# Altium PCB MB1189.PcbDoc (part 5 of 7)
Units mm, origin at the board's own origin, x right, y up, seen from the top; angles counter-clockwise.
Board outline 60.03 x 127.03 mm, 6 copper layers (TOP, L2_GND, L3_VCC, L4_SIG, L5_GND, BOTTOM), stack 1.58 mm thick; 273 components, 264 nets, 1114 pads, 811 vias.
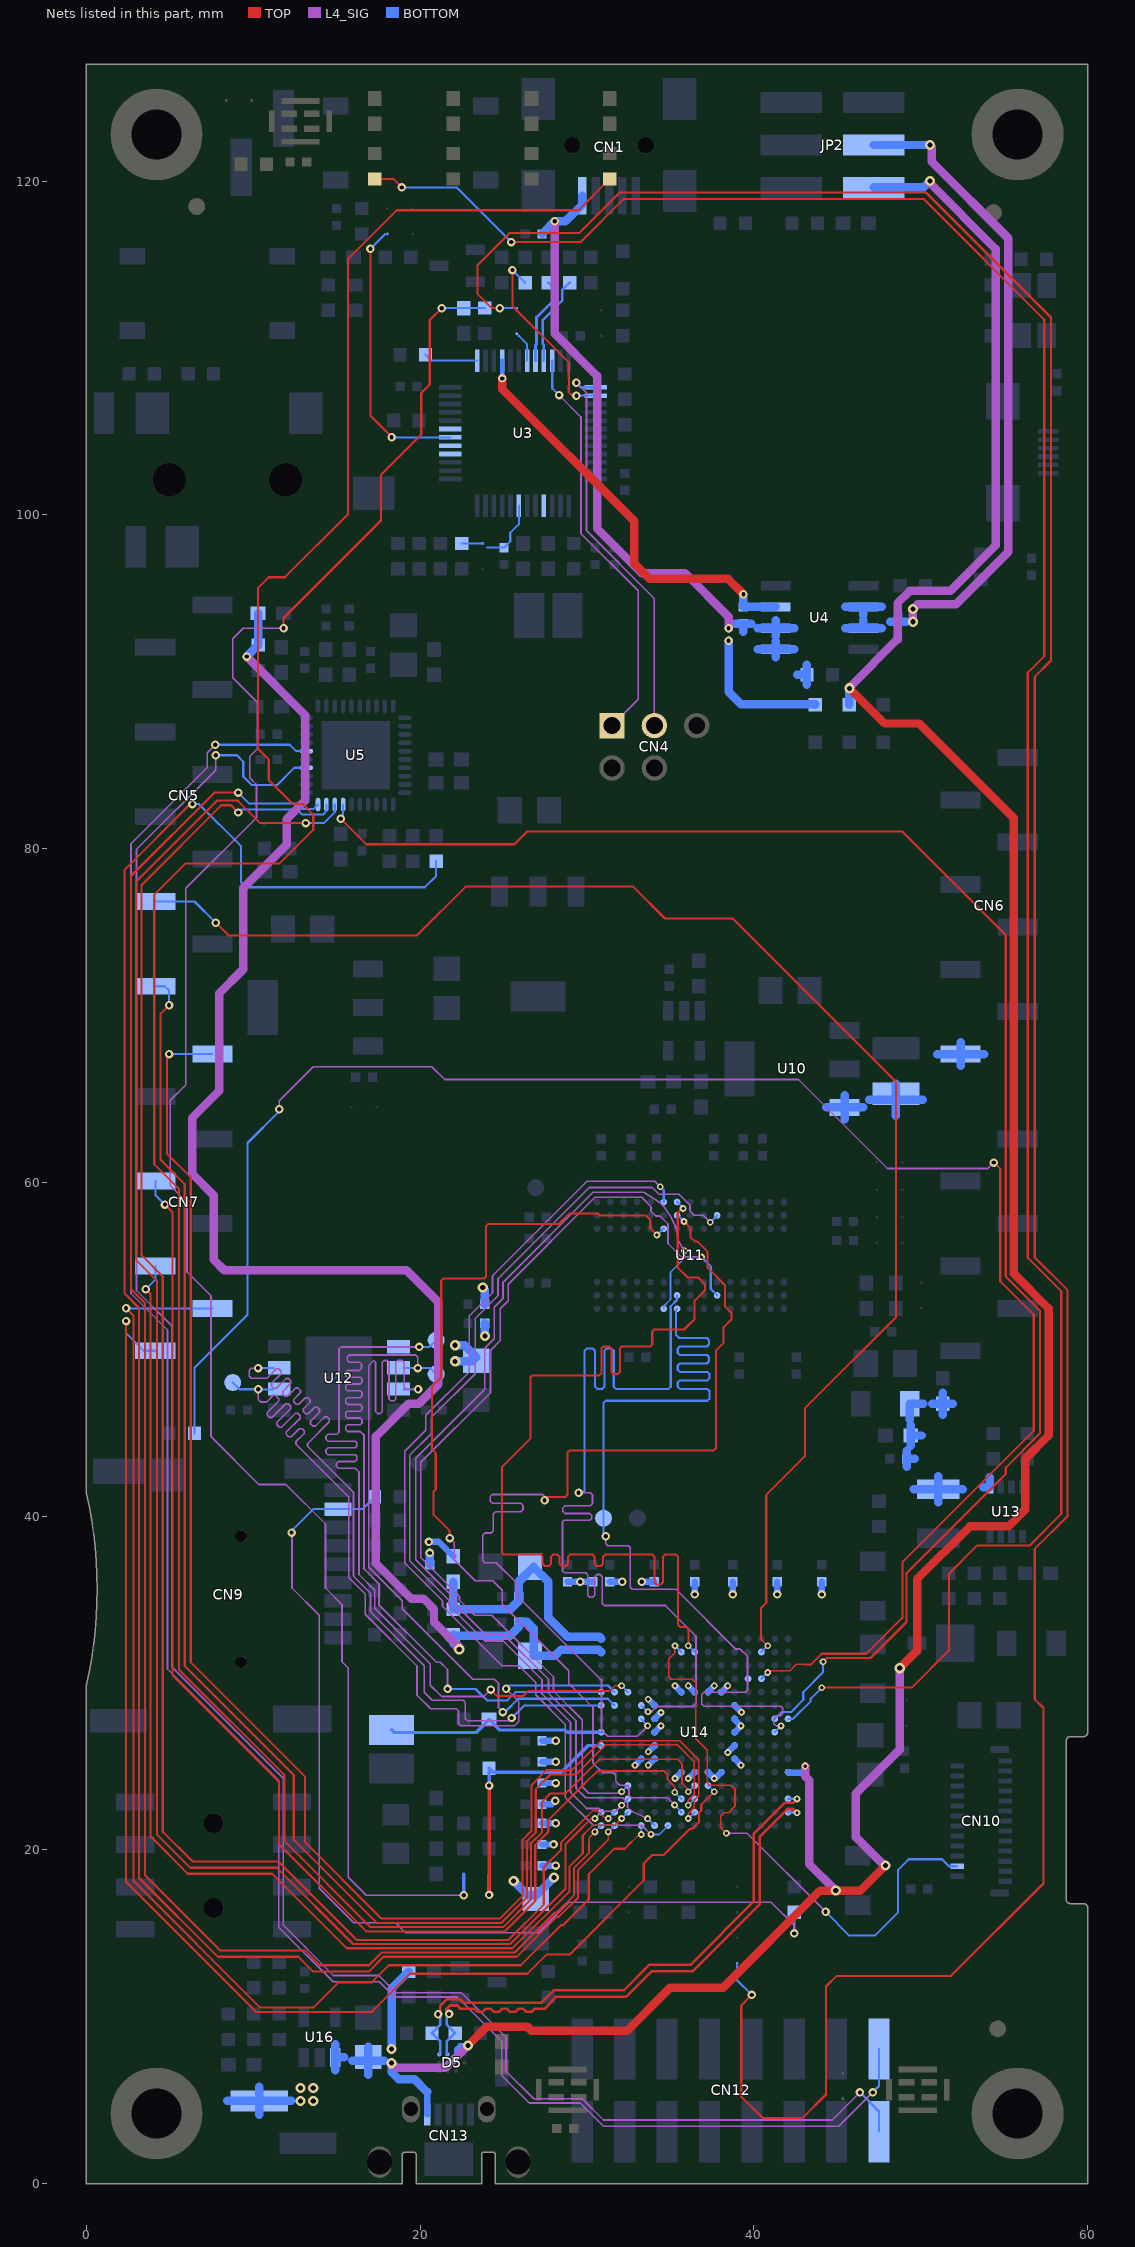
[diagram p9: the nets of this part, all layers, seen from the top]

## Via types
v1: diameter 0.61/0.61/0.61 (per signal layer), hole 0.305, TOP to BOTTOM, 321 vias
v2: diameter 0.508/0.508/0.508 (per signal layer), hole 0.254, TOP to BOTTOM, 247 vias
v3: diameter 0.406/0.406/0.406 (per signal layer), hole 0.203, TOP to BOTTOM, 243 vias

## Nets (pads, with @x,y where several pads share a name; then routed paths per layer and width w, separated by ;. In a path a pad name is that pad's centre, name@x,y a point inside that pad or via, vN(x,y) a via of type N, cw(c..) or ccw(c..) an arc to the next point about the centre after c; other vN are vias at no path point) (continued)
PE0: U11.K9 U14.A6 | length 58.9
  L4_SIG w0.102: v3(33.833,20.921) 33.816,20.921 33.274,21.463 30.378,21.463 28.702,23.139 28.702,27.511 26.924,29.289 26.924,30.023 25.921,31.026 24.905,31.026 21.336,34.595 21.336,34.925 19.075,37.186 19.075,43.891 20.333,45.148 20.333,46.038 22.936,48.641 22.936,51.994 24.333,53.391 24.333,54.407 29.997,60.071 34.061,60.071 v3(34.392,59.741)
  BOTTOM w0.102: v3(33.833,20.921) 34.319,20.921 U14.A6@34.849,21.451
  BOTTOM w0.127: v3(34.392,59.741) 34.595,59.537 U11.K9@34.595,58.826
PE1: U11.K1 U14.A5 | length 61.9
  L4_SIG w0.102: v3(33.631,21.869) 32.69,22.301 32.427,22.564 32.427,22.821 32.13,23.118 29.917,23.118 29.337,23.698 29.337,27.739 27.686,29.39 27.686,30.229 24.986,32.928 23.891,32.928 22.047,34.773 22.047,35.076 19.736,37.388 19.736,43.459 23.876,47.6 23.876,50.063 24.435,50.622 24.435,52.527 24.968,53.061 24.968,54.026 30.353,59.411 33.401,59.411 34.392,58.776 34.557,58.61 35.049,57.896 35.361,57.22 35.464,56.527 v3(35.839,55.905)
  BOTTOM w0.102: U11.K1@34.595,52.426 34.595,52.578 35.001,52.984 35.001,54.61 35.839,55.448 v3(35.839,55.905)
  BOTTOM w0.127: v3(33.631,21.869) U14.A5@34.049,21.451
PE3: R46.2 U14.A2 | length 121.3
  TOP w0.102: 31.14,20.472 31.272,20.604 v3(31.272,21.074)
  TOP w0.127: v2(6.35,82.677) 6.223,82.677 2.286,78.74 2.286,53.34 3.15,52.476 3.15,18.313 7.874,13.589 12.7,13.589 13.589,12.7 16.913,12.7 17.802,13.589 25.781,13.589 28.181,15.989 28.308,15.989 29.464,17.145 29.464,18.796 31.14,20.472
  BOTTOM w0.102: v3(31.272,21.074) U14.A2@31.649,21.451
  BOTTOM w0.127: v2(6.35,82.677) 6.731,82.677 9.271,80.137 9.271,77.978 9.563,77.686 20.282,77.686 20.955,78.359 R46.2@20.955,79.248
PE4: U5.40 U14.A1 | length 108.6
  TOP w0.102: 30.128,20.472 30.128,20.73 v3(30.472,21.074)
  TOP w0.127: v2(9.093,83.363) 7.671,83.363 2.667,78.359 2.667,53.594 3.505,52.756 3.505,18.466 8.001,13.97 13.081,13.97 13.97,13.081 16.934,13.081 17.696,13.843 25.676,13.843 28.076,16.243 28.203,16.243 29.21,17.25 29.21,18.901 30.128,19.82 30.128,20.472
  BOTTOM w0.102: v3(30.472,21.074) U14.A1@30.849,21.451
  BOTTOM w0.127: v2(9.093,83.363) 9.754,82.702 12.634,82.702 12.952,82.384 13.615,82.384 U5.40@13.879,82.648
PE5: U5.38 U14.B1 | length 107
  TOP w0.102: 29.87,21.488 30.256,21.874 v3(30.472,21.874)
  TOP w0.127: v2(13.144,81.534) 10.414,81.534 9.068,82.88 7.823,82.88 2.975,78.032 2.975,55.344 4.216,54.102 4.216,20.93 6.223,18.923 11.405,18.923 15.977,14.351 25.4,14.351 28.702,17.653 28.702,20.32 29.87,21.488
  BOTTOM w0.102: v3(30.472,21.874) U14.B1@30.849,22.251
  BOTTOM w0.127: v2(13.144,81.534) 14.224,81.534 14.879,82.189 U5.38@14.879,82.648
PE6: U5.39 U14.B2 | length 106.1
  TOP w0.102: 29.87,21.869 30.353,22.352 30.607,22.352 31.085,21.874 v3(31.272,21.874)
  TOP w0.127: v2(9.093,82.169) 8.661,82.601 8.077,82.601 3.302,77.826 3.302,55.626 4.572,54.356 4.572,21.082 6.35,19.304 11.481,19.304 16.18,14.605 25.295,14.605 27.407,16.717 27.407,18.971 28.448,20.012 28.448,20.447 29.87,21.869
  BOTTOM w0.102: v3(31.272,21.874) U14.B2@31.649,22.251
  BOTTOM w0.127: v2(9.093,82.169) 9.271,82.347 12.631,82.347 12.935,82.042 14.173,82.042 14.379,82.248 U5.39@14.379,82.648
PF6: U12.7 U14.K2 | length 48.2
  L4_SIG w0.102: v2(19.875,47.599) 19.177,47.599 19.05,47.726 19.05,49.2 18.923,49.327 18.641,49.327 18.539,49.225 18.539,47.015 18.438,46.914 18.234,46.914 18.133,47.015 18.133,49.225 18.031,49.327 17.828,49.327 17.726,49.225 17.726,46.271 17.607,46.152 17.439,46.152 17.32,46.271 17.32,49.225 17.218,49.327 16.916,49.025 16.916,36.932 18.923,34.925 18.923,34.455 23.152,30.226 24.435,30.226 24.689,29.972 24.689,28.522 v2(24.954,28.258)
  BOTTOM w0.127: U12.7@19.013,47.599 v2(19.875,47.599) ; v2(24.954,28.258) 25.082,28.258 25.88,29.055 31.245,29.055 U14.K2@31.649,28.651
PF7: U12.3 U14.K1 | length 48
  L4_SIG w0.102: v2(10.287,48.869) 9.881,48.87 9.754,48.743 9.754,48.387 9.881,48.26 10.82,48.26 10.988,48.428 11.383,48.823 11.527,48.823 11.671,48.679 11.671,48.536 11.09,47.955 11.09,47.787 11.209,47.668 11.377,47.668 11.958,48.248 12.102,48.248 12.246,48.104 12.246,47.961 11.754,47.469 11.754,47.301 11.873,47.182 12.041,47.182 12.533,47.673 12.677,47.673 12.821,47.529 12.821,47.386 12.426,46.991 12.426,46.848 12.57,46.703 12.713,46.703 13.108,47.098 13.252,47.098 13.396,46.954 13.396,46.811 13.001,46.416 13.001,46.272 13.145,46.128 13.288,46.128 13.683,46.523 13.827,46.523 13.971,46.379 13.971,46.236 13.431,45.696 13.431,45.523 13.553,45.4 13.726,45.4 14.265,45.939 14.437,45.939 14.558,45.818 14.558,45.647 13.246,44.336 13.246,44.183 16.002,41.427 16.002,36.398 17.018,35.382 17.018,34.265 20.244,31.039 20.244,29.439 20.726,28.956 22.581,28.956 22.708,28.829 22.708,27.864 22.835,27.737 25.352,27.737 25.479,27.864 v2(25.479,27.9)
  BOTTOM w0.127: v2(10.287,48.869) U12.3@11.213,48.869 ; v2(25.479,27.9) 26.23,28.651 U14.K1@30.849,28.651
PF8: TP6.1 U12.5 U14.L3 | length 49.8
  TOP w0.102: 29.87,29.515 31.36,29.515 31.674,29.828 v3(32.072,29.828)
  TOP w0.127: v2(24.232,29.604) 24.625,29.21 26.162,29.21 26.467,29.515 29.87,29.515
  L4_SIG w0.102: v2(19.939,50.139) 15.265,50.139 15.138,50.012 15.138,45.027 15.011,44.9 14.47,44.9 14.351,44.781 14.351,44.613 14.47,44.494 16.104,44.494 16.205,44.392 16.205,44.189 16.104,44.088 14.47,44.088 14.351,43.968 14.351,43.8 14.47,43.681 16.104,43.681 16.205,43.58 16.205,43.376 16.104,43.275 15.088,43.275 14.986,43.173 14.986,42.97 15.088,42.868 16.104,42.868 16.332,42.64 16.332,36.5 17.272,35.56 17.272,34.468 20.599,31.14 20.599,29.87 21.285,29.185 23.812,29.185 v2(24.232,29.604)
  BOTTOM w0.127: U12.5@19.013,50.139 v2(19.939,50.139) 20.548,50.139 TP6.1@20.955,50.546 ; v3(32.072,29.828) U14.L3@32.449,29.451
PF9: TP7.1 U12.2 U14.L2 | length 49.6
  L4_SIG w0.102: v2(10.288,47.6) 10.288,46.989 10.439,46.838 10.795,46.838 11.201,47.244 11.328,47.244 11.532,47.041 11.532,46.901 10.836,46.205 10.836,46.035 10.956,45.914 11.127,45.914 11.948,46.735 12.091,46.735 12.235,46.591 12.235,46.447 11.401,45.613 11.401,45.47 11.545,45.326 11.689,45.326 12.523,46.16 12.666,46.16 12.81,46.016 12.81,45.872 11.976,45.038 11.976,44.895 12.12,44.751 12.264,44.751 12.755,45.242 12.924,45.242 13.043,45.123 13.043,44.955 12.551,44.463 12.551,44.319 15.723,41.148 15.723,36.322 16.713,35.331 16.713,34.112 19.812,31.013 19.812,29.261 20.625,28.448 22.174,28.448 22.301,28.321 22.301,27.559 22.428,27.432 25.654,27.432 25.911,27.689 25.911,28.89 v2(25.146,29.654)
  BOTTOM w0.127: TP7.1@8.763,48.006 9.169,47.6 v2(10.288,47.6) ; v2(10.288,47.6) U12.2@11.213,47.599 ; v2(25.146,29.654) 25.336,29.845 31.255,29.845 U14.L2@31.649,29.451
PF10: TP5.1 U12.6 U14.L1 | length 48.1
  L4_SIG w0.102: v2(19.851,48.869) 19.851,49.53 19.724,49.657 15.748,49.657 15.621,49.53 15.621,49.352 15.748,49.225 16.358,49.225 16.485,49.098 16.485,48.853 16.358,48.726 15.646,48.726 15.545,48.625 15.545,48.422 15.646,48.32 16.408,48.32 16.51,48.218 16.51,48.015 16.408,47.914 15.646,47.914 15.545,47.812 15.545,47.609 15.646,47.507 16.408,47.507 16.51,47.406 16.51,47.202 16.408,47.101 15.646,47.101 15.545,46.999 15.545,46.796 15.646,46.694 16.408,46.694 16.51,46.593 16.51,46.39 16.408,46.288 15.646,46.288 15.545,46.186 15.545,45.983 15.646,45.882 16.408,45.882 16.51,45.78 16.51,45.577 16.408,45.475 15.646,45.475 15.545,45.374 15.545,45.17 15.646,45.069 16.408,45.069 16.637,44.84 16.637,36.83 17.526,35.941 17.526,34.696 20.98,31.242 21.209,31.242 21.641,30.81 v2(21.641,29.642)
  BOTTOM w0.127: U12.6@19.013,48.869 v2(19.851,48.869) 20.6,48.869 TP5.1@20.955,48.514 ; v2(21.641,29.642) 23.317,29.642 24.003,28.956 25.222,28.956 25.717,29.451 U14.L1@30.849,29.451
PF11: U11.J9 U14.P8 | length 59
  TOP w0.127: v3(35.757,58.434) 35.689,58.434 35.433,58.178 35.433,54.889 36.017,54.305 36.652,54.305 37.059,53.899 37.059,53.518 36.449,52.908 36.449,51.816 35.814,51.181 34.036,51.181 33.909,51.054 33.909,50.292 33.782,50.165 32.092,50.165 31.965,50.038 31.965,48.641 31.838,48.514 31.584,48.514 31.457,48.641 31.457,50.038 31.33,50.165 30.988,50.165 30.861,50.038 30.861,48.565 30.734,48.438 26.733,48.438 26.607,48.311 26.607,44.64 24.892,42.926 24.892,37.821 25.019,37.694 27.211,37.694 27.338,37.567 27.338,37.135 27.465,37.008 27.719,37.008 27.846,37.135 27.846,37.567 27.973,37.694 28.227,37.694 28.354,37.567 28.354,37.135 28.481,37.008 28.735,37.008 28.862,37.135 28.862,37.567 28.989,37.694 30.325,37.694 30.452,37.567 30.452,37.135 30.579,37.008 30.833,37.008 30.96,37.135 30.96,37.567 31.087,37.694 33.912,37.694 34.039,37.567 34.039,36.017 34.166,35.89 34.42,35.89 34.547,36.017 34.547,37.567 34.674,37.694 35.331,37.694 35.458,37.567 35.458,33.477 35.585,33.35 35.945,33.35 36.072,33.223 v3(36.072,32.228)
  BOTTOM w0.127: U11.J9@35.395,58.826 35.408,58.826 35.757,58.477 v3(35.757,58.434) ; v3(36.072,32.228) U14.P8@36.449,31.851
PG2: R57.1 U14.M13 | length 109.9
  TOP w0.102: v3(40.826,30.628) 40.932,30.734 42.164,30.734 42.545,31.115 43.028,31.115
  TOP w0.127: 43.028,31.115 43.434,31.115 44.069,31.75 46.736,31.75 48.895,33.909 48.895,37.236 56.769,45.11 56.769,52.07 54.762,54.077 54.762,60.808 v2(54.381,61.189)
  L4_SIG w0.102: v2(11.557,64.389) 11.557,64.897 13.589,66.929 20.701,66.929 21.463,66.167 42.672,66.167 48.006,60.833 54.026,60.833 v2(54.381,61.189)
  BOTTOM w0.127: R57.1@6.477,44.958 6.477,48.895 9.652,52.07 9.652,62.357 11.557,64.262 v2(11.557,64.389) ; U14.M13@40.449,30.251 v3(40.826,30.628)
PG3: U14.M12
PG6: R2.1 U14.J15 | length 142.8
  TOP w0.127: R2.1@17.272,120.142 18.39,120.142 v2(18.898,119.634) ; v2(25.451,116.357) 29.616,116.357 32.207,118.948 50.165,118.948 57.404,111.709 57.404,91.542 56.413,90.551 56.413,55.474 58.42,53.467 58.42,40.132 56.515,38.227 53.365,38.227 51.689,36.551 51.689,31.953 49.454,29.718 v3(44.069,29.718)
  BOTTOM w0.127: v2(18.898,119.634) 22.174,119.634 v2(25.451,116.357) ; U14.J15@42.049,27.851 42.342,27.851 43.402,28.911 43.402,29.051 v3(44.069,29.718)
PG7: U5.37 U14.J14 | length 100.6
  TOP w0.127: v2(15.24,81.788) 16.764,80.264 25.654,80.264 26.416,81.026 48.895,81.026 55.093,74.828 55.093,54.356 57.15,52.299 57.15,44.958 55.093,42.901 55.093,42.52 49.149,36.576 49.149,33.655 46.99,31.496 44.374,31.496 v3(44.145,31.267)
  BOTTOM w0.127: v2(15.24,81.788) 15.379,81.927 U5.37@15.379,82.648 ; U14.J14@41.249,27.851 41.648,28.25 42.22,28.25 42.956,28.986 42.956,29.443 44.145,30.632 v3(44.145,31.267)
PG8: TP3.1 U11.J1 U14.H14 | length 58
  L4_SIG w0.102: v2(31.115,38.798) 31.115,38.354 31.242,38.227 32.461,38.227 32.588,38.1 32.588,35.738 32.715,35.611 35.331,35.611 38.913,32.029 39.188,32.029 39.62,31.598 39.62,29.566 39.493,29.439 37.008,29.439 36.881,29.312 36.881,28.728 37.008,28.601 41.605,28.601 41.732,28.474 41.732,28.169 41.605,28.042 41.326,28.042 41.199,27.915 41.199,27.555 41.326,27.428 v3(41.626,27.428)
  BOTTOM w0.127: v2(31.115,38.798) 30.988,38.925 TP3.1@30.988,39.878 30.988,46.787 31.115,46.914 37.211,46.914 37.338,47.041 37.338,47.498 37.211,47.625 35.56,47.625 35.433,47.752 35.433,48.006 35.56,48.133 37.211,48.133 37.338,48.26 37.338,48.514 37.211,48.641 35.56,48.641 35.433,48.768 35.433,49.022 35.56,49.149 37.186,49.149 37.313,49.276 37.313,49.53 37.186,49.657 35.56,49.657 35.433,49.784 35.433,50.038 35.56,50.165 37.186,50.165 37.313,50.292 37.313,50.546 37.186,50.673 35.522,50.673 35.331,50.863 35.331,52.363 U11.J1@35.395,52.426 ; U14.H14@41.249,27.051 v3(41.626,27.428)
PG9: CN7.1 U14.D9 | length 82.1
  TOP w0.127: v2(2.375,51.689) 2.375,18.072 10.16,10.287 17.094,10.287 19.38,12.573 26.416,12.573 27.559,13.716 28.951,13.716 33.401,18.166 33.401,19.177 33.909,19.685 34.596,19.685 36.158,21.247 36.305,21.247 36.703,21.645 36.703,22.209 36.847,22.353 36.847,22.694 v3(37.626,23.474)
  BOTTOM w0.102: U14.D9@37.249,23.851 v3(37.626,23.474)
  BOTTOM w0.127: v2(2.375,51.689) 2.375,50.965 3.429,49.911 CN7.1@4.127,49.911
PG10: CN5.1 U14.C8 | length 93
  TOP w0.102: 29.87,25.044 31.115,26.289 35.399,26.289 36.427,25.261 36.427,23.327 36.072,22.971 v3(36.072,22.674)
  TOP w0.127: v2(4.953,70.612) 4.445,70.104 4.445,61.341 5.893,59.893 5.893,31.013 12.421,24.486 12.421,20.599 17.399,15.621 24.873,15.621 26.391,17.139 26.391,20.505 26.924,21.039 26.924,23.622 27.813,24.511 29.337,24.511 29.87,25.044
  BOTTOM w0.127: CN5.1@4.127,71.755 4.699,71.755 4.953,71.501 v2(4.953,70.612) ; v3(36.072,22.674) U14.C8@36.449,23.051
PG11: CN7.8 U14.B8 | length 91.6
  TOP w0.102: 29.87,25.552 30.861,26.543 35.56,26.543 36.703,25.4 36.703,23.241 36.427,22.965 36.427,22.526 36.072,22.171 v3(36.072,21.874)
  TOP w0.127: v2(4.953,67.691) 4.826,67.564 4.826,61.722 6.248,60.3 6.248,31.242 13.106,24.384 13.106,20.447 17.678,15.875 24.768,15.875 26.137,17.244 26.137,20.611 26.67,21.144 26.67,23.876 27.559,24.765 29.083,24.765 29.87,25.552
  BOTTOM w0.127: v2(4.953,67.691) CN7.8@7.556,67.691 ; v3(36.072,21.874) U14.B8@36.449,22.251
PG12: CN7.5 U14.C7 | length 76.5
  TOP w0.102: 29.87,23.971 29.87,23.982 30.607,24.718 34.62,24.718 34.827,24.511 34.827,24.206 35.255,23.778 v3(35.255,23.444)
  TOP w0.127: v2(4.699,58.674) 5.156,58.217 5.156,30.455 11.532,24.079 11.532,20.345 16.764,15.113 25.084,15.113 26.899,16.928 26.899,20.295 27.673,21.069 27.673,21.774 29.87,23.971
  BOTTOM w0.127: CN7.5@4.127,60.071 4.127,59.245 v2(4.699,58.674) ; v3(35.255,23.444) U14.C7@35.649,23.051
PG13: CN7.3 U14.B3 | length 70.8
  TOP w0.102: 29.87,20.98 30.353,21.463 31.661,21.463 v3(32.072,21.874)
  TOP w0.127: v2(3.556,53.594) 3.835,53.315 3.835,20.803 6.071,18.567 11.125,18.567 15.596,14.097 25.527,14.097 28.956,17.526 28.956,19.007 29.743,19.794 29.743,20.853 29.87,20.98
  BOTTOM w0.102: v3(32.072,21.874) U14.B3@32.449,22.251
  BOTTOM w0.127: v2(3.556,53.594) 4.127,54.165 CN7.3@4.127,54.991
PG14: CN7.2 U14.A4 | length 79
  TOP w0.102: 32.664,20.472 33.11,20.918 v3(33.249,20.918)
  TOP w0.127: v2(2.375,52.451) 2.819,52.006 2.819,18.136 10.414,10.541 13.589,10.541 15.113,12.065 17.101,12.065 18.117,13.081 26.035,13.081 28.435,15.481 28.562,15.481 30.099,17.018 30.099,18.542 31.623,20.066 32.258,20.066 32.664,20.472
  BOTTOM w0.102: v3(33.249,20.918) U14.A4@33.249,21.451
  BOTTOM w0.127: v2(2.375,52.451) CN7.2@7.556,52.451
PG15: U11.K7 U14.B7 | length 58.7
  TOP w0.127: v2(21.768,38.684) 21.768,39.116 20.803,40.081 20.803,41.478 20.93,41.605 20.93,43.79 20.701,44.018 20.701,47.752 21.26,48.311 21.26,54.102 21.387,54.229 23.825,54.229 23.952,54.356 23.952,57.379 24.079,57.506 28.321,57.506 28.956,58.141 30.632,58.141 30.759,58.014 33.528,58.014 33.786,57.756 33.786,57.247 v3(34.188,56.845)
  L4_SIG w0.102: v2(21.768,38.684) 22.034,38.417 22.034,37.376 23.292,36.119 24.358,36.119 24.917,35.559 24.917,34.722 28.905,30.735 28.905,29.966 29.307,29.565 29.313,29.565 30.353,28.525 30.353,25.192 30.907,24.638 31.567,24.638 31.716,24.489 31.716,24.126 31.967,23.876 32.385,23.876 32.512,23.749 32.512,23.241 32.639,23.114 34.819,23.114 v3(35.246,22.687)
  BOTTOM w0.127: v3(34.188,56.845) 34.569,57.226 U11.K7@34.595,57.226 ; v3(35.246,22.687) 35.649,22.284 U14.B7@35.649,22.251
PH0: R131.1 SB19.2 U14.G1 | length 16.3
  TOP w0.203: v2(24.13,17.297) v2(24.13,23.851)
  BOTTOM w0.203: v2(24.13,17.297) SB19.2@24.13,18.542 ; v2(24.13,23.851) R131.1@24.13,24.892 24.384,24.638 28.448,24.638 30.061,26.251 U14.G1@30.849,26.251
PH1: C83.1 U14.H1 X2.1 | length 13.3
  BOTTOM w0.203: X2.1@18.288,27.185 18.442,27.031 23.348,27.031 C83.1@24.13,27.813 24.765,27.178 28.702,27.178 28.829,27.051 U14.H1@30.849,27.051
PH2: U11.J2 U14.K4 | length 57.5
  L4_SIG w0.102: v2(29.489,41.402) 30.201,41.402 30.328,41.275 30.328,40.742 30.201,40.615 28.677,40.615 28.55,40.488 28.55,40.284 28.677,40.157 30.158,40.157 30.277,40.038 30.277,39.87 30.158,39.751 28.626,39.751 28.524,39.649 28.524,36.728 28.651,36.601 29.921,36.601 30.048,36.474 30.048,35.247 30.167,35.128 30.335,35.128 30.455,35.247 30.455,36.373 30.582,36.5 30.785,36.5 30.912,36.373 30.912,34.773 31.039,34.646 34.696,34.646 36.525,32.817 36.525,28.778 36.331,28.584 34.172,28.584 33.858,28.27 v3(33.655,28.27)
  BOTTOM w0.102: U14.K4@33.249,28.651 33.63,28.27 v3(33.655,28.27)
  BOTTOM w0.127: v2(29.489,41.402) 29.718,41.402 29.845,41.529 29.845,49.911 29.972,50.038 30.353,50.038 30.48,49.911 30.48,47.752 30.607,47.625 30.912,47.625 31.039,47.752 31.039,49.911 31.166,50.038 31.471,50.038 31.598,49.911 31.598,47.752 31.725,47.625 34.891,47.625 35.018,47.752 35.018,52.578 35.395,52.955 U11.J2@35.395,53.226
PH3: U11.J8 U14.J4 | length 57.5
  TOP w0.127: v2(27.457,40.945) 27.457,41.021 27.584,41.148 28.702,41.148 28.829,41.275 28.829,43.815 28.956,43.942 37.592,43.942 37.719,44.069 37.719,49.911 38.189,50.381 38.189,51.321 38.659,51.791 38.659,52.172 38.278,52.553 38.278,53.823 37.224,54.877 37.224,55.842 36.601,56.464 36.449,56.464 36.195,56.718 36.195,57.277 v3(35.814,57.658)
  L4_SIG w0.102: v2(27.457,40.945) 27.457,41.173 27.33,41.3 24.333,41.3 24.206,41.173 24.206,40.894 24.333,40.767 26.035,40.767 26.162,40.64 26.162,40.386 26.035,40.259 24.511,40.259 24.384,40.132 24.384,39.116 24.257,38.989 23.876,38.989 23.749,38.862 23.749,37.338 23.876,37.211 24.562,37.211 25.832,35.941 25.832,35.204 30.861,30.175 30.861,27.178 31.242,26.797 33.02,26.797 33.63,27.407 v3(33.63,27.435)
  BOTTOM w0.102: U14.J4@33.249,27.851 33.249,27.816 v3(33.63,27.435)
  BOTTOM w0.127: U11.J8@35.395,58.026 35.446,58.026 v3(35.814,57.658)
PH6: CN5.3 U14.P13 | length 89.1
  TOP w0.127: v2(7.747,75.565) 8.509,74.803 19.812,74.803 22.733,77.724 32.766,77.724 34.671,75.819 38.735,75.819 48.514,66.04 48.514,51.918 43.053,46.457 43.053,43.586 40.742,41.275 40.742,34.798 40.437,34.493 40.437,32.618 v3(40.826,32.228)
  BOTTOM w0.127: CN5.3@4.127,76.835 6.477,76.835 v2(7.747,75.565) ; U14.P13@40.449,31.851 v3(40.826,32.228)
PI4: U11.F8 U14.C3 | length 58.4
  L4_SIG w0.102: v3(32.072,22.674) 31.716,22.318 30.895,22.318 30.734,22.479 29.972,22.479 29.007,23.444 29.007,27.638 27.305,29.34 27.305,30.178 24.971,32.512 23.876,32.512 21.717,34.671 21.717,34.975 19.38,37.312 19.38,43.663 20.663,44.945 20.663,45.91 23.292,48.539 23.292,51.841 24.663,53.213 24.663,54.229 30.124,59.69 33.909,59.69 34.315,59.284 35.509,59.284 36.17,58.623 36.17,58.293 36.424,58.039 36.957,58.039 v3(37.389,57.607)
  BOTTOM w0.102: v3(32.072,22.674) U14.C3@32.449,23.051
  BOTTOM w0.127: v3(37.389,57.607) 37.795,58.013 U11.F8@37.795,58.026
PI5: U11.F2 U14.D3 | length 58.7
  L4_SIG w0.102: v3(32.072,23.474) 31.991,23.393 30.095,23.393 29.718,23.77 29.718,27.789 27.991,29.516 27.991,30.355 24.284,34.061 23.266,34.061 22.352,34.976 22.352,35.203 20.041,37.514 20.041,43.231 24.219,47.409 24.219,49.949 24.79,50.521 24.79,52.426 25.273,52.908 25.273,53.899 30.48,59.106 33.274,59.106 33.833,58.547 33.833,58.268 34.112,57.988 34.366,57.988 34.849,57.506 34.849,56.337 35.662,55.524 v3(36.855,55.524)
  BOTTOM w0.102: v3(32.072,23.474) U14.D3@32.449,23.851
  BOTTOM w0.127: v3(36.855,55.524) 37.414,54.966 37.414,53.607 U11.F2@37.795,53.226
PJ2: CN10.22 U14.P7 | length 35.6
  TOP w0.102: v3(35.272,32.228) 35.272,31.817 34.9,31.445 34.9,30.378 35.052,30.226 36.322,30.226 36.512,30.035 36.512,26.657 37.211,25.959 37.211,24.003 37.338,23.876 38.608,23.876 38.862,23.622 38.862,22.606 38.485,22.229 38.279,22.229 38.274,22.225 38.227,22.225 38.02,22.018 38.02,21.327 v3(38.354,20.993)
  L4_SIG w0.102: v3(38.354,20.993) 39.586,20.993 v2(44.298,16.282)
  BOTTOM w0.127: v3(35.272,32.228) U14.P7@35.649,31.851 ; v2(44.298,16.282) 45.72,14.859 47.244,14.859 48.641,16.256 48.641,18.796 49.276,19.431 51.275,19.431 51.689,19.017 CN10.22@52.175,19.017
PK3: R5.1 U14.D8 | length 163.1
  TOP w0.102: 29.87,24.536 30.763,25.429 35.419,25.429 35.627,25.221 35.627,25.206 35.687,25.146 35.687,24.003 36.072,23.618 v3(36.072,23.474)
  TOP w0.127: 29.87,24.536 28.715,23.381 27.813,23.381 27.305,22.873 27.305,21.06 26.645,20.4 26.645,17.033 24.978,15.367 17.018,15.367 11.849,20.536 11.849,24.498 5.537,30.81 5.537,59.614 4.064,61.087 4.064,77.238 5.947,79.121 11.579,79.121 13.589,81.131 13.589,82.042 12.954,82.677 12.361,82.677 10.922,84.116 10.922,85.344 10.287,85.979 10.287,95.631 10.922,96.266 11.887,96.266 15.684,100.063 15.684,115.354 18.593,118.262 29.489,118.262 R5.1@31.369,120.142
  BOTTOM w0.102: v3(36.072,23.474) U14.D8@36.449,23.851
PWR_ENN: R38.2 U3.28 U4.3 | length 25.5
  TOP w0.508: v2(24.912,108.184) 24.912,107.549 32.829,99.632 32.829,97.092 33.757,96.164 38.456,96.164 v2(39.37,95.25)
  BOTTOM w0.254: v2(24.912,108.184) U3.28@24.912,109.252
  BOTTOM w0.508: v2(39.37,95.25) R38.2@39.37,94.488 U4.3@41.318,94.488
SPKR_OUTAN: CN12.15 U5.6 | length 127.6
  L4_SIG w0.102: v2(7.722,86.233) 7.239,85.75 7.239,84.861 2.667,80.289 2.667,53.34 4.851,51.156 4.851,30.836 11.532,24.155 11.532,15.342 14.783,12.09 17.551,12.09 18.466,11.176 22.225,11.176 24.892,8.509 24.892,6.477 26.543,4.826 29.591,4.826 30.988,3.429 45.085,3.429 v2(47.117,5.461)
  BOTTOM w0.127: v2(7.722,86.233) 12.192,86.233 12.577,85.848 U5.6@13.179,85.848 ; v2(47.117,5.461) 47.498,5.842 CN12.15@47.498,8.063
SPKR_OUTAP: CN12.16 U5.4 | length 126.9
  L4_SIG w0.102: v2(7.747,85.598) 7.747,84.709 2.997,79.959 2.997,53.518 5.105,51.41 5.105,30.963 11.786,24.282 11.786,15.494 14.808,12.471 17.526,12.471 18.567,11.43 22.479,11.43 25.146,8.763 25.146,6.731 26.797,5.08 29.718,5.08 30.988,3.81 44.704,3.81 v2(46.355,5.461)
  BOTTOM w0.127: v2(7.747,85.598) 9.017,85.598 9.398,85.217 9.398,84.328 9.906,83.82 11.43,83.82 12.458,84.848 U5.4@13.179,84.848 ; v2(46.355,5.461) 47.498,4.318 CN12.16@47.498,3.113
STL_USB_DM: R14.2 U3.32 | length 5.4
  BOTTOM w0.155: U3.32@26.912,109.252 26.912,110.18 26.971,110.239 26.971,111.838 28.13,112.997 28.13,113.474 R14.2@27.686,113.919
STL_USB_DP: R13.2 U3.33 | length 5.4
  BOTTOM w0.155: U3.33@27.412,109.252 27.412,110.18 27.352,110.239 27.352,111.68 28.511,112.84 28.511,113.474 R13.2@28.956,113.919
STLK_MCO: C26.1 R35.2 SB19.1 | length 120.3
  TOP w0.127: v2(11.811,93.218) 11.811,93.828 17.653,99.67 17.653,102.413 20.066,104.826 20.066,107.315 20.574,107.823 20.574,111.684 v2(21.285,112.395)
  L4_SIG w0.102: v2(11.811,93.218) 9.398,93.218 8.763,92.583 8.763,90.246 10.236,88.773 10.236,85.979 9.779,85.522 9.779,84.252 10.185,83.845 10.185,81.864 5.944,77.622 5.944,65.837 5.029,64.922 5.029,59.817 6.02,58.826 6.02,54.635 7.468,53.188 7.468,44.755 10.325,41.897 11.951,41.897 14.326,39.522 14.326,35.687 15.316,34.696 15.316,31.267 15.684,30.899 15.684,18.351 16.764,17.272 v2(22.606,17.272)
  BOTTOM w0.127: v2(21.285,112.395) C26.1@22.606,112.395 R35.2@23.876,112.395
  BOTTOM w0.203: v2(22.606,17.272) SB19.1@22.606,18.542
STM_JTCK: CN4.3 U3.37 | length 23.7
  L4_SIG w0.102: v2(29.362,107.925) 29.972,107.315 29.972,99.06 34.036,94.996 CN4.3@34.036,87.376
  BOTTOM w0.127: v2(29.362,107.925) 29.635,107.652 U3.37@30.512,107.652
STM_JTMS: CN4.1 U3.34 | length 24.7
  L4_SIG w0.102: v2(28.321,107.188) 29.642,105.867 29.642,98.882 33.071,95.453 33.071,88.951 CN4.1@31.496,87.376
  BOTTOM w0.127: U3.34@27.912,109.252 27.912,107.597 v2(28.321,107.188)
STM_RST: C12.2 R30.1 SB4.2 U3.7 | length 5.2
  BOTTOM w0.127: R30.1@22.479,98.298 SB4.2@23.749,98.298 ; 24.003,98.044 C12.2@25.019,98.044 25.4,98.425 25.4,98.933 25.912,99.445 U3.7@25.912,100.552
SWIM_PU_CTRL: U3.4
SWO: SB3.2 SB7.1 | length 176.7
  TOP w0.127: v2(24.765,112.395) 24.282,112.395 23.444,113.233 23.444,114.986 25.349,116.891 29.515,116.891 31.953,119.329 50.317,119.329 57.81,111.836 57.81,91.275 56.832,90.297 56.832,55.499 58.801,53.53 58.801,40.005 56.832,38.036 56.832,29.019 57.353,28.499 57.353,17.983 51.816,12.446 44.958,12.446 44.323,11.811 44.323,5.334 42.926,3.937 40.513,3.937 39.243,5.207 39.243,10.668 v2(39.878,11.303)
  BOTTOM w0.127: v2(24.765,112.395) SB3.2@25.781,112.395 ; SB7.1@38.989,13.208 38.989,12.192 v2(39.878,11.303)
T_JRST: U3.19
T_JTDI: U3.17
T_JTDO: U3.16
T_NRST: SB2.1 U3.18 | length 16.7
  TOP w0.127: v2(17.018,115.951) 17.018,105.943 18.288,104.673 v2(18.288,104.652)
  BOTTOM w0.127: v2(17.018,115.951) 17.907,116.84 SB2.1@18.034,116.84 ; v2(18.288,104.652) U3.18@21.812,104.652
T_SWDIO_IN: R20.1 U3.25 | length 3.2
  BOTTOM w0.127: R20.1@20.32,109.601 20.669,109.252 U3.25@23.412,109.252
T_SWO: SB3.1 U3.31 | length 1.7
  BOTTOM w0.127: 25.908,110.744 26.412,110.24 U3.31@26.412,109.252
U5V_ST_LINK: C14.2 JP2.3 U4.6 U4.7 | length 44.4
  L4_SIG w0.508: v1(49.53,93.599) v1(49.53,94.361) 49.809,94.64 52.095,94.64 55.245,97.79 55.245,116.586 50.673,121.158 50.673,122.047 v1(50.546,122.174)
  BOTTOM w0.508: 45.473,93.218 U4.7@46.566,93.218 ; 45.473,94.488 U4.6@46.566,94.488 ; 46.566,93.701 U4.7@46.566,93.218 ; 46.566,94.005 U4.6@46.566,94.488 ; JP2.3@47.179,122.174 v1(50.546,122.174) ; 47.659,93.218 U4.7@46.566,93.218 ; 47.659,94.488 U4.6@46.566,94.488 ; 48.158,93.599 C14.2@48.641,93.599 ; 48.641,94.082 C14.2@48.641,93.599 ; 49.124,93.599 C14.2@48.641,93.599
USB_FS1_N: D5.D3 R160.2 U14.C15 | length 33.1
  TOP w0.155: v2(21.069,10.147) 21.196,10.274 21.196,10.63 21.615,11.049 22.383,11.049 22.586,10.846 27.28,10.846 28.016,11.582 32.202,11.582 33.726,13.106 36.189,13.106 39.98,16.897 39.98,20.951 41.856,22.828 42.359,22.828 v3(42.582,23.051)
  BOTTOM w0.155: v2(21.069,10.147) 21.209,10.008 21.209,9.525 R160.2@20.701,9.017 21.204,8.514 21.204,7.799 D5.D3@21.145,7.739 ; U14.C15@42.049,23.051 v3(42.582,23.051)
USB_FS1_P: D5.C3 R159.2 U14.B15 | length 33
  TOP w0.155: v2(21.73,10.163) 21.577,10.315 21.577,10.472 21.773,10.668 22.225,10.668 22.428,10.465 23.26,10.465 23.437,10.287 23.747,10.287 23.925,10.465 24.235,10.465 24.413,10.287 24.723,10.287 24.9,10.465 25.21,10.465 25.388,10.287 25.698,10.287 25.876,10.465 26.186,10.465 26.363,10.287 26.673,10.287 26.851,10.465 27.438,10.465 28.174,11.201 32.36,11.201 33.884,12.725 36.347,12.725 40.361,16.739 40.361,20.793 42.014,22.447 42.358,22.447 v3(42.582,22.223)
  BOTTOM w0.155: D5.C3@21.645,7.739 21.585,7.799 21.585,8.504 R159.2@22.098,9.017 21.59,9.525 21.59,10.023 v2(21.73,10.163) ; U14.B15@42.049,22.251 42.554,22.251 v3(42.582,22.223)
USB_RENUMN: R15.2 U3.38 | length 11.5
  TOP w0.127: v2(25.527,114.681) 25.527,112.522 28.905,109.144 28.905,108.193 28.907,108.191 28.907,107.781 28.905,107.779 28.905,107.366 29.119,107.152 v2(29.362,107.152)
  BOTTOM w0.127: v2(25.527,114.681) R15.2@26.289,113.919 ; v2(29.362,107.152) U3.38@30.512,107.152
uSD_D1: CN9.8 R86.2 R135.2 | length 60.6
  L4_SIG w0.102: v2(12.294,39.014) 12.319,38.989 12.319,35.687 13.945,34.061 13.945,17.704 16.027,15.621 18.533,15.621 19.122,15.032 27.072,15.032 28.905,16.866 41.021,16.866 42.418,15.469 v2(42.418,14.986)
  BOTTOM w0.127: v2(12.294,39.014) 12.294,39.116 13.595,40.417 CN9.8@15.071,40.417 16.541,40.417 R86.2@17.272,41.148 ; v2(42.418,14.986) R135.2@42.418,16.256
VBUS_FS1: C101.1 CN13.1 D3.1 D5.B3 JP2.5 R155.1 U14.E15 U16.1 | length 186.1
  TOP w0.508: v1(22.86,8.28) 23.978,9.398 26.416,9.398 26.67,9.144 32.385,9.144 34.976,11.735 38.151,11.735 43.967,17.551 v1(44.907,17.551) 46.38,17.551 v1(47.879,19.05) ; v1(45.72,89.611) 47.828,87.503 49.911,87.503 55.575,81.839 55.575,54.534 57.658,52.451 57.658,44.831 56.261,43.434 56.261,40.386 55.258,39.383 52.946,39.383 49.784,36.22 49.784,31.928 v1(48.743,30.886)
  L4_SIG w0.508: v1(18.288,7.211) 18.565,6.934 21.514,6.934 v1(22.86,8.28) ; v3(43.078,25.019) 43.078,24.409 43.307,24.181 43.307,19.152 v1(44.907,17.551) ; v1(45.72,89.611) 45.72,89.662 48.616,92.558 48.616,94.717 49.352,95.453 51.765,95.453 54.483,98.171 54.483,115.951 50.546,119.888 v1(50.546,120.015) ; v1(47.879,19.05) 47.815,19.05 46.101,20.764 46.101,23.368 48.743,26.01 v1(48.743,30.886)
  BOTTOM w0.254: D5.B3@22.145,7.739 22.145,8.048 22.377,8.28 v1(22.86,8.28)
  BOTTOM w0.381: CN13.1@20.417,4.135 20.417,5.491 ; U14.E15@42.049,24.651 42.087,24.613 42.901,24.613 43.078,24.79 v3(43.078,25.019)
  BOTTOM w0.508: 14.92,6.788 U16.1@14.92,7.563 ; 14.92,8.338 U16.1@14.92,7.563 ; 15.441,7.563 U16.1@14.92,7.563 ; 15.925,7.366 C101.1@16.891,7.366 ; 16.891,6.527 C101.1@16.891,7.366 ; C101.1@16.891,8.205 C101.1@16.891,7.366 ; 17.857,7.366 C101.1@16.891,7.366 ; v1(18.288,7.211) 18.288,6.68 18.707,6.261 19.647,6.261 20.417,5.491 ; v1(18.288,8.07) 18.288,11.684 R155.1@19.304,12.7 ; D3.1@45.72,88.628 v1(45.72,89.611) ; JP2.5@47.179,119.634 50.165,119.634 v1(50.546,120.015)
VDD_MCU: C53.1 C54.1 C60.1 C67.1 C68.1 C69.1 C70.1 C71.1 C72.1 C73.1 C74.1 C75.1 C84.1 C88.1 C89.1 C90.1 C91.1 C92.1 C95.1 C98.1 JP5.2 L5.1 U14.E7 U14.E8 U14.E9 U14.E10 U14.F4 U14.F5 U14.F11 U14.G5 U14.G11 U14.H5 U14.H11 U14.J5 U14.J11 U14.K5 U14.K11 U14.L7 U14.L8 U14.L9 U14.L10 | length 38
  BOTTOM w0.381: v2(20.523,38.456) 21.107,38.456 L5.1@21.971,37.592 ; C95.1@27.305,19.054 v2(28.118,19.054) ; C92.1@27.305,20.32 v2(27.991,20.32) ; C91.1@27.305,21.59 v2(28.118,21.59) ; C90.1@27.305,22.733 27.889,22.733 v2(28.092,22.936) ; C89.1@27.305,24.003 v2(28.118,24.003) ; C88.1@27.305,25.273 v2(28.118,25.273) ; C84.1@27.305,26.543 v2(28.118,26.543) ; C74.1@28.829,36.068 v2(29.591,36.068) C73.1@30.353,36.068 ; C72.1@31.369,36.068 v2(32.105,36.067) ; v3(32.872,25.074) U14.F4@33.249,25.451 ; v2(33.274,36.068) C71.1@34.036,36.068 ; v3(33.672,25.074) U14.F5@34.049,25.451 ; v3(33.672,25.874) U14.G5@34.049,26.251 ; v3(33.672,29.028) U14.K5@34.049,28.651 ; U14.H5@34.049,27.051 34.426,27.428 v3(34.434,27.428) ; U14.J5@34.049,27.851 34.426,28.228 v3(34.434,28.228) ; v3(35.272,24.274) U14.E7@35.649,24.651 ; v3(35.272,29.828) U14.L7@35.649,29.451 ; v3(36.072,24.274) U14.E8@36.449,24.651 ; v3(36.072,29.828) U14.L8@36.449,29.451 ; v2(36.449,35.306) C70.1@36.449,36.068 ; U14.E9@37.249,24.651 v3(37.626,24.274) 37.672,24.274 U14.E10@38.049,24.651 ; U14.L9@37.249,29.451 v3(37.626,29.828) ; U14.L10@38.049,29.451 v3(38.426,29.828) ; v3(38.43,25.832) U14.G11@38.849,26.251 ; v2(38.735,35.306) C69.1@38.735,36.068 ; U14.F11@38.849,25.451 v3(39.226,25.074) ; U14.H11@38.849,27.051 v3(39.226,27.428) 38.849,27.805 U14.J11@38.849,27.851 ; U14.K11@38.849,28.651 v3(39.255,28.245) ; v2(41.402,35.306) C68.1@41.402,36.068 ; v2(44.069,35.306) C67.1@44.069,36.068
  BOTTOM w0.508: 8.433,4.953 JP5.2@10.351,4.953 ; 10.351,4.114 JP5.2@10.351,4.953 ; 10.351,5.792 JP5.2@10.351,4.953 ; 12.269,4.953 JP5.2@10.351,4.953 ; C75.1@20.574,37.084 v2(20.574,37.795) ; v1(22.098,49.276) 23.114,49.276 23.368,49.53 22.657,50.241 v1(22.098,50.241) ; v1(23.749,53.696) 23.876,53.569 C53.1@23.876,52.705 ; v1(23.876,50.8) C54.1@23.876,51.562 ; v1(25.603,18.136) 26.467,17.272 26.924,17.272 26.949,17.272 v1(28.016,18.339)
  other v1: 12.827,4.953 13.589,4.953 12.827,5.715 13.589,5.715
VDDA: C65.1 C77.2 L5.2 R123.1 U14.R1 | length 15.3
  BOTTOM w0.508: L5.2@21.971,36.068 R123.1@21.971,34.417 25.4,34.417 25.908,34.925 C77.2@25.908,35.179 25.908,36.068 26.797,36.957 27.686,36.068 27.686,33.909 28.829,32.766 30.734,32.766 U14.R1@30.849,32.651
VIN: C36.1 CN6.8 U10.3 | length 13
  BOTTOM w0.508: 44.336,64.502 U10.3@45.441,64.502 ; 45.441,63.79 U10.3@45.441,64.502 ; 45.441,65.214 U10.3@45.441,64.502 ; 46.547,64.502 U10.3@45.441,64.502 ; 46.913,64.96 C36.1@48.514,64.96 ; 48.514,64.007 C36.1@48.514,64.96 ; C36.1@48.514,65.914 C36.1@48.514,64.96 ; 50.115,64.96 C36.1@48.514,64.96 ; 50.977,67.691 CN6.8@52.387,67.691 ; 52.387,66.979 CN6.8@52.387,67.691 ; 52.387,68.403 CN6.8@52.387,67.691 ; 53.798,67.691 CN6.8@52.387,67.691
VL: C61.1 C63.2 C64.2 L3.2 L4.1 U13.1 | length 13.1
  BOTTOM w0.508: 49.149,42.951 C64.2@49.149,43.434 ; 49.149,43.917 C64.2@49.149,43.434 ; 49.352,45.77 C61.1@49.352,46.736 50.14,46.736 ; 49.403,44.221 C63.2@49.403,44.831 ; 49.403,45.441 C63.2@49.403,44.831 ; 49.58,41.605 L4.1@51.054,41.605 ; 49.632,43.434 C64.2@49.149,43.434 ; 50.051,44.831 C63.2@49.403,44.831 ; 50.698,46.736 L3.2@51.308,46.736 ; 51.054,40.817 L4.1@51.054,41.605 ; 51.054,42.393 L4.1@51.054,41.605 ; 51.308,46.088 L3.2@51.308,46.736 ; 51.308,47.384 L3.2@51.308,46.736 ; 51.918,46.736 L3.2@51.308,46.736 ; 52.528,41.605 L4.1@51.054,41.605 ; 53.736,41.734 U13.1@54.143,41.734 54.143,42.331
VREF+: C13.2 C78.2 C80.1 R41.1 R123.2 U14.P1 | length 96
  L4_SIG w0.508: v2(9.601,91.516) 13.106,88.011 13.106,82.88 11.989,81.763 11.989,80.239 9.398,77.648 9.398,72.771 7.95,71.323 7.95,65.481 6.325,63.856 6.325,60.528 7.62,59.233 7.62,55.372 8.255,54.737 19.177,54.737 21.082,52.832 21.082,47.904 19.914,46.736 19.304,46.736 17.348,44.78 17.348,37.16 19.456,35.052 20.193,35.052 20.828,34.417 20.828,33.655 22.339,32.144 v1(22.339,32.017)
  BOTTOM w0.508: v2(9.601,91.516) R41.1@10.287,92.202 C13.2@10.287,94.107 ; v1(22.339,32.017) 21.971,32.385 R123.2@21.971,32.893 22.022,32.842 25.4,32.842 25.908,33.35 C78.2@25.908,33.655 26.416,33.655 26.797,33.274 26.797,31.623 28.067,31.623 28.448,32.004 30.696,32.004 U14.P1@30.849,31.851
VUSB_ST_LINK: CN1.1 D4.1 R9.2 R38.1 R42.1 U4.1 U4.2 | length 52
  L4_SIG w0.508: v2(28.067,117.602) 28.067,110.871 30.607,108.331 30.607,99.187 33.274,96.52 35.865,96.52 38.481,93.904 v2(38.481,93.218)
  BOTTOM w0.508: R9.2@27.305,116.84 v2(28.067,117.602) 28.702,117.602 29.718,118.618 CN1.1@29.718,119.126 ; v2(38.481,92.456) 38.481,89.408 39.243,88.646 43.67,88.646 D4.1@43.688,88.628 ; 38.887,93.472 R38.1@39.37,93.472 ; 39.37,92.989 R38.1@39.37,93.472 ; 39.853,93.472 R38.1@39.37,93.472 ; 40.225,91.948 U4.1@41.318,91.948 ; 40.225,93.218 U4.2@41.318,93.218 ; 41.318,91.465 U4.1@41.318,91.948 ; 41.318,92.431 U4.1@41.318,91.948 ; 41.318,92.735 U4.2@41.318,93.218 ; 41.318,93.701 U4.2@41.318,93.218 ; 42.411,91.948 U4.1@41.318,91.948 ; 42.411,93.218 U4.2@41.318,93.218 ; 42.583,90.424 R42.1@43.18,90.424 ; 43.18,89.814 R42.1@43.18,90.424 ; 43.18,91.034 R42.1@43.18,90.424
pads on no net: CN1. CN1.7 CN1.8 CN1.9 CN2.7 CN2.8 CN3. CN3.5 CN3.7 CN4.5 CN6.1 CN9. CN9.11 CN9.12 CN9.13 CN9.14 CN10. CN10.1 CN10.9 CN10.13 CN10.17 CN10.20 CN11. CN11.2 CN11.6 CN11.8 D5.A2 D5.B1 D5.B2 D5.C2 U3.11 U3.14 U3.21 U3.40 U3.41 U3.42 U3.43 U3.45 U3.46 U5.7 U5.9 U5.20 U5.21 U5.22 U5.23 U5.24 U5.25 U5.26 U5.29 U5.30 U5.36 U11.E3 U11.E7 U11.H3 U11.H7 U11.K2 U11.K3 U12.9 U13.5 U14.B9 U14.B10 U14.C2 U14.C4 U14.C5 U14.C6 U14.C9 U14.D7 U14.D10 U14.E3 U14.F3 U14.G3 U14.G4 U14.H3 U14.M9 U14.N8 U14.N10 U14.R6 U14.R7
copper on no net: | length 42.1
  TOP w0.254: 13.335,58.547 13.335,59.944 14.732,59.944 14.732,58.547 13.335,58.547 ; 13.335,60.579 13.335,61.976 14.732,61.976 14.732,60.579 13.335,60.579
  L4_SIG w0.254: 18.669,58.547 18.669,59.944 20.066,59.944 20.066,58.547 18.669,58.547 ; 18.669,60.579 18.669,61.976 20.066,61.976 20.066,60.579 18.669,60.579
  BOTTOM w0.102: v3(31.272,22.674) 31.649,23.051 ; v3(32.072,24.274) 32.449,24.651 ; v3(32.072,25.074) 32.449,25.451 ; v3(32.072,25.874) 32.449,26.251 ; v3(32.072,27.428) 32.449,27.051 ; v3(32.872,22.674) 33.249,23.051 ; v3(32.872,25.874) 33.249,26.251 ; v3(33.672,22.674) 34.049,23.051 ; 38.049,23.851 v3(38.426,23.474)
  BOTTOM w0.127: v3(34.472,22.674) 34.849,23.051 ; v3(34.472,33.028) 34.849,32.651 ; v3(35.272,33.028) 35.649,32.651 ; 37.249,22.251 v3(37.626,21.874) ; 37.249,30.251 v3(37.626,30.628) ; v3(37.664,31.428) 38.041,31.051 38.049,31.051 ; 38.049,22.251 v3(38.426,21.874)
  BOTTOM w0.254: 22.225,58.547 22.225,59.944 23.622,59.944 23.622,58.547 22.225,58.547 ; 22.225,60.579 22.225,61.976 23.622,61.976 23.622,60.579 22.225,60.579

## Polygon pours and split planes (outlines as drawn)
GND on TOP "TOP_GND_P034" (solid, remove dead copper, pour order 34): 22.86,25.527 25.654,25.527 25.781,25.4 25.781,17.526 24.625,16.37 18.047,16.37 15.989,18.428 15.989,28.08 15.989,28.562 16.256,28.829 19.558,28.829 22.86,25.527
GND on TOP "TOP_GND_P035" (solid, remove dead copper, pour order 35): 18.923,91.313 25.019,85.217 25.019,80.899 24.638,80.518 16.891,80.518 12.573,84.836 12.573,88.417 10.973,90.018 10.973,91.669 10.973,95.098 11.379,95.504 12.294,95.504 16.535,99.746 16.535,102.286 16.537,102.288 16.537,102.694 19.215,105.372 19.215,107.455 19.215,107.836 19.456,108.077 19.456,112.624 19.964,113.132 21.692,113.132 21.971,112.852 21.971,110.947 21.209,110.185 21.209,104.927 18.923,102.641 18.923,91.313
GND on TOP "TOP_GND_P033" (solid, remove dead copper, pour order 33): 23.114,90.424 23.114,96.901 23.495,97.282 31.75,97.282 32.131,96.901 32.131,90.297 31.877,90.043 23.495,90.043 23.114,90.424
BLGND on TOP "TOP_BLGND_P032" (solid, remove dead copper, pour order 32): 47.396,47.346 53.95,47.346 54.534,46.761 54.534,45.39 51.943,42.799 47.066,42.799 46.482,43.383 46.482,46.431 47.396,47.346
VBUS_FS1 on BOTTOM "BOTTOM_VBUS_FS1_P043" (solid, remove dead copper, pour order 43): 18.669,6.477 18.415,6.223 14.859,6.223 14.605,6.477 14.605,8.509 14.605,8.636 14.859,8.89 18.161,8.89 18.669,8.382 18.669,6.477
VIN on BOTTOM "BOTTOM_VIN_P056" (solid, remove dead copper, pour order 56): 46.355,63.373 43.942,63.373 43.307,64.008 43.307,65.405 43.688,65.786 45.974,65.786 46.291,65.786 46.736,66.23 50.292,66.23 50.8,66.739 50.8,68.707 51.054,68.961 51.181,68.961 53.721,68.961 54.102,68.58 54.102,64.77 52.705,63.373 50.927,63.373 50.863,63.309 46.419,63.309 46.355,63.373
GND on BOTTOM "BOTTOM_GND_P055" (solid, remove dead copper, pour order 55): 50.292,70.866 50.292,67.31 50.038,67.056 46.99,67.056 45.847,68.199 43.434,68.199 42.418,69.215 42.418,73.152 42.672,73.406 45.085,73.406 45.339,73.152 45.339,71.882 45.593,71.628 49.53,71.628 50.292,70.866
BLGND on BOTTOM "BOTTOM_BLGND_P049" (solid, remove dead copper, pour order 49): 45.847,53.213 47.371,53.213 47.752,52.832 47.752,45.974 48.387,45.339 48.387,43.18 48.387,42.799 48.26,42.672 47.117,42.672 46.99,42.799 46.99,43.18 46.99,44.196 45.466,45.72 45.466,52.832 45.847,53.213
NETC37_1 on BOTTOM "BOTTOM_NETC37_1_P063" (solid, remove dead copper, pour order 63): 24.511,75.057 25.578,75.057 25.984,75.463 25.984,80.035 26.213,80.264 27.762,80.264 27.965,80.264 28.194,80.035 28.194,79.832 28.194,75.26 28.397,75.057 32.385,75.057 32.766,75.057 32.893,74.93 32.893,63.5 32.639,63.246 24.765,63.246 19.304,63.246 18.796,63.246 18.415,63.627 18.415,65.786 18.669,66.04 18.986,66.358 18.986,70.294 19.685,70.993 23.368,70.993 23.876,71.501 23.876,74.422 24.511,75.057
GND on BOTTOM "BOTTOM_GND_P061" (solid, remove dead copper, pour order 61): 24.257,75.692 23.241,74.676 23.241,72.517 22.86,72.136 21.514,72.136 19.05,72.136 18.796,72.39 18.796,74.803 18.923,74.93 21.971,77.978 21.971,81.407 21.971,81.534 21.971,81.915 23.749,83.693 24.13,83.693 25.654,83.693 26.162,83.185 26.162,81.026 26.035,80.899 25.654,80.899 25.527,80.772 25.273,80.518 25.273,76.2 25.273,75.946 25.019,75.692 24.257,75.692
+1V8 on BOTTOM "BOTTOM_+1V8_P060" (solid, remove dead copper, pour order 60): 12.7,76.708 12.7,72.644 13.843,71.501 14.224,71.501 18.034,71.501 18.288,71.247 18.288,69.596 18.034,69.342 13.97,69.342 13.843,69.215 12.827,68.199 9.652,68.199 9.271,68.58 9.271,76.2 9.271,76.708 9.271,77.089 9.525,77.343 12.446,77.343 12.7,77.089 12.7,76.708
E5V on BOTTOM "BOTTOM_E5V_P054" (solid, remove dead copper, pour order 54): 41.529,64.389 38.227,64.389 37.719,64.897 37.719,69.469 39.116,70.866 39.116,73.025 39.37,73.279 41.402,73.279 41.656,73.025 41.656,69.088 42.291,68.453 43.434,67.31 43.434,66.294 41.529,64.389
GND on BOTTOM "BOTTOM_GND_P047" (solid, remove dead copper, pour order 47): 16.002,76.708 16.002,74.803 16.256,74.549 16.637,74.168 17.78,74.168 18.161,73.787 18.161,72.263 18.034,72.136 17.78,72.136 14.478,72.136 13.462,73.152 13.462,76.708 13.462,76.962 13.462,77.343 13.589,77.47 15.875,77.47 16.002,77.343 16.002,77.089 16.002,76.708
+5V on BOTTOM "BOTTOM_+5V_P052" (solid, remove dead copper, pour order 52): 31.369,82.169 31.369,76.708 30.48,75.819 29.083,75.819 28.829,76.073 28.702,76.2 28.702,80.645 28.448,80.899 27.686,80.899 27.432,81.153 27.432,84.455 27.432,84.709 27.559,84.836 30.099,84.836 30.353,84.582 30.353,84.201 30.353,83.185 31.369,82.169
GND on BOTTOM "BOTTOM_GND_P057" (solid, remove dead copper, pour order 57): 20.066,5.207 20.066,3.048 20.32,2.794 23.241,2.794 23.495,3.048 23.495,5.715 23.622,5.842 24.13,5.842 24.384,5.588 26.416,5.588 26.924,5.08 26.924,1.016 26.67,0.762 26.467,0.559 24.689,0.559 24.663,0.584 24.663,1.93 24.511,2.083 23.597,2.083 23.47,1.956 23.47,0.508 19.964,0.508 19.964,1.93 19.812,2.083 18.898,2.083 18.745,1.93 18.745,0.508 16.637,0.508 16.383,0.762 16.383,4.826 17.272,5.715 19.558,5.715 20.066,5.207
NETL4_2 on BOTTOM "BOTTOM_NETL4_2_P050" (solid, remove dead copper, pour order 50): 51.054,37.592 53.975,37.592 54.356,37.973 54.356,38.989 54.229,39.116 53.086,39.116 52.578,39.624 49.784,39.624 49.149,39.624 48.641,39.116 48.641,31.623 48.895,31.369 50.292,31.369 50.292,32.169 50.292,34.011 50.546,34.265 50.546,37.084
VL on BOTTOM "BOTTOM_VL_P053" (solid, remove dead copper, pour order 53): 52.451,44.069 53.848,42.672 54.229,42.672 54.356,42.545 54.356,41.402 54.229,41.275 53.213,41.275 52.768,40.831 52.451,40.513 52.197,40.513 49.403,40.513 48.895,41.021 48.895,43.307 48.895,45.466 48.895,47.244 49.149,47.498 52.07,47.498 52.451,47.117 52.451,44.069
GND on BOTTOM "BOTTOM_GND_P058" (solid, remove dead copper, pour order 58): 21.768,27.33 19.99,27.33 19.837,27.483 19.837,28.219 19.761,28.296 16.764,28.296 16.713,28.245 16.713,23.851 16.815,23.749 19.837,23.749 19.863,23.774 19.863,24.486 19.964,24.587 21.793,24.587 21.971,24.409 21.971,22.86 21.717,22.606 21.463,22.606 20.396,22.606 20.396,21.869 20.345,21.819 19.406,21.819 19.406,19.812 19.482,19.736 20.066,19.736 20.396,19.406 20.396,19.126 20.447,19.075 21.438,19.075 21.59,18.923 21.59,17.386 21.488,17.285 21.374,17.285 17.145,17.285 15.989,18.44 15.989,28.08 15.989,28.562 16.256,28.829 20.447,28.829 20.676,28.829 22.911,28.829 23.063,28.677 23.063,27.508 22.885,27.33 22.708,27.33 21.768,27.33
VDD_MCU on BOTTOM "BOTTOM_VDD_MCU_P044" (solid, remove dead copper, pour order 44): 8.128,6.223 13.843,6.223 13.97,6.096 13.97,4.064 13.843,3.937 8.128,3.937 8.001,4.064 8.001,6.096 8.128,6.223
+3V3 on BOTTOM "BOTTOM_+3V3_P046" (solid, remove dead copper, pour order 46): 18.034,68.707 14.859,68.707 14.732,68.58 14.732,67.564 14.097,66.929 12.954,66.929 12.827,66.802 12.827,66.675 12.827,65.659 12.827,64.262 13.208,63.881 14.732,63.881 14.859,64.008 14.859,65.278 14.859,65.405 14.986,65.532 15.113,65.532 16.256,65.532 16.383,65.659 16.383,66.802 17.907,66.802 18.224,67.12 18.224,68.516 18.034,68.707
GND on BOTTOM "BOTTOM_GND_P062" (solid, remove dead copper, pour order 62): 23.495,90.043 23.114,90.424 23.114,96.088 23.673,96.647 32.004,96.647 32.131,96.52 32.131,90.297 31.877,90.043 23.495,90.043
BLGND on BOTTOM "BOTTOM_BLGND_P040" (solid, remove dead copper, pour order 40): 59.055,45.72 59.055,40.64 59.055,30.988 58.928,30.861 57.531,30.861 57.277,31.115 57.277,39.37 57.15,39.497 53.467,39.497 53.086,39.878 53.086,40.64 53.467,41.021 57.15,41.021 57.658,41.529 57.658,43.942 57.023,44.577 53.34,44.577 53.213,44.704 53.213,46.228 53.213,46.482 53.467,46.736 58.674,46.736 59.055,46.355 59.055,45.72
A on BOTTOM "BOTTOM_A_P039" (solid, remove dead copper, pour order 39): 56.261,37.592 56.642,37.592 56.769,37.465 56.769,31.115 56.134,30.48 51.054,30.48 50.8,30.734 50.8,33.782 51.181,34.163 55.118,34.163 55.372,34.417 55.372,37.465 55.372,37.973 55.499,38.1 55.753,38.1 56.261,37.592
+3V3 on BOTTOM "BOTTOM_+3V3_P045" (solid, remove dead copper, pour order 45): 9.398,3.429 15.113,3.429 15.494,3.048 15.494,1.651 15.113,1.27 9.271,1.27 9.017,1.524 9.017,3.048 9.398,3.429
+5V on BOTTOM "BOTTOM_+5V_P059" (solid, remove dead copper, pour order 59): 40.005,126.238 41.529,126.238 44.196,126.238 44.577,125.857 44.577,118.745 44.323,118.491 43.053,118.491 42.799,118.237 42.799,117.094 42.799,116.84 42.799,116.713 42.672,116.586 40.259,116.586 40.132,116.713 40.132,116.967 40.132,117.221 40.132,117.475 40.132,118.237 39.751,118.618 39.497,118.872 39.497,125.73 40.005,126.238
U5V_ST_LINK on BOTTOM "BOTTOM_U5V_ST_LINK_P041" (solid, remove dead copper, pour order 41): 45.466,94.869 49.149,94.869 49.784,94.869 49.911,94.742 49.911,93.345 49.784,93.218 48.387,93.218 48.006,92.837 45.466,92.837 45.339,92.964 45.339,94.742 45.466,94.869
+3V3_ST_LINK on BOTTOM "BOTTOM_+3V3_ST_LINK_P042" (solid, remove dead copper, pour order 42): 35.687,67.31 36.068,66.929 36.068,63.627 35.687,63.246 34.925,63.246 34.544,63.627 34.544,66.548 33.909,67.183 33.909,68.834 34.036,68.961 34.163,68.961 35.433,68.961 35.687,68.707 35.687,67.31
+5V on BOTTOM "BOTTOM_+5V_P051" (solid, remove dead copper, pour order 51): 47.244,76.327 52.324,76.327 52.451,76.454 57.404,76.454 57.658,76.2 57.658,74.295 57.531,74.168 47.244,74.168 46.99,74.422 46.99,76.073 47.244,76.327
VUSB_ST_LINK on BOTTOM "BOTTOM_VUSB_ST_LINK_P048" (solid, remove dead copper, pour order 48): 38.227,93.98 42.926,93.98 43.561,93.345 43.561,89.916 43.307,89.662 39.878,89.662 39.624,89.916 39.624,91.821 39.497,91.948 38.1,91.948 37.973,92.075 37.973,93.726 38.227,93.98
+1V8 on L4_SIG "L4_SIG_+1V8_P037" (solid, remove dead copper, pour order 37): 12.319,91.313 18.542,91.313 19.558,91.313 21.209,89.662 21.209,79.248 21.209,78.867 18.288,75.946 10.541,75.946 10.16,76.327 10.16,77.597 12.7,80.137 17.78,80.137 19.05,81.407 19.05,88.011 18.415,88.646 12.7,88.646 12.192,89.154 12.192,91.186 12.319,91.313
